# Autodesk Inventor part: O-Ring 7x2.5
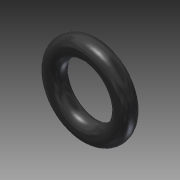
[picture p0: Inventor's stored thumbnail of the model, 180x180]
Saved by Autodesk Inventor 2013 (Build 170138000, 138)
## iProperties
Created: 2012-07
Part Number: O-Ring 7x2.5
Material: Gummi, Silikon
Document SubType Name: Modeling
Designer: rYan
Mass: 0.183127 g
Surface Area: 2.34403 cm^2
Volume: 0.146502 cm^3
Density: 1.25 g/cm^3
Author: rYan
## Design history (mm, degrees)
sketch "Skizze1"
  geometry: L1 (3.5, -5.084)-(3.5, 3.724); L2 (-1.2, 0)-(7.2, 0) reference; L3 (0, 5.425)-(0, -4.831); L4 (0, 7.527)-(0, -7.186) reference; C1 r 1.25 at (4.75, 0); 1 further point
  constraints: 4 end point, 1 centre point, 1 collinear, 1 point on line, 1 tangent, 1 vertical
  dimensions: "d1" = 2.5 diameter of C1; "d3" = 7 diameter of L1 L3
revolve "Umdrehung1" sketch "Skizze1" stored, may be unused: angle "d2" = 90 deg
node "Volumenkörper1"
